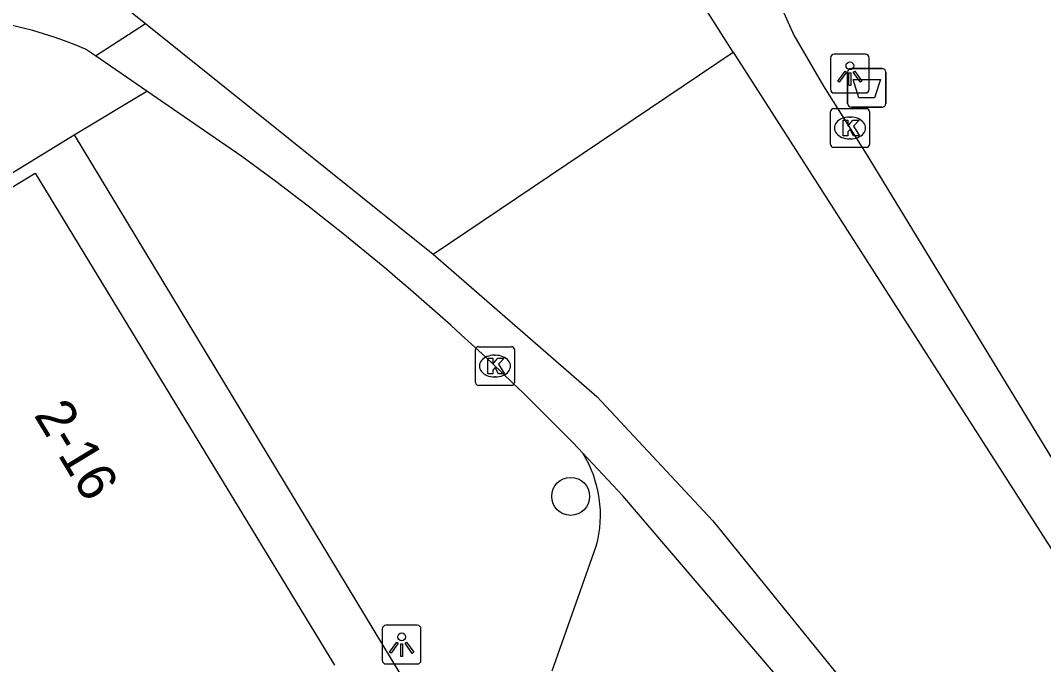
# Model space of a CAD drawing. Extents: x 159888 to 160757, y 384031 to 384746.
# Drawn here: x 160266.23 to 160292.59, y 384671.18 to 384687.78 of the extents above; entities that cross this region are included whole.
import ezdxf

# ---------------------------------------------------------------- set-up
doc = ezdxf.new("R2010")
doc.units = 0
for name, color, linetype in [('IMGEO_Afvalbak', 7, 'Continuous'), ('IMGEO_Boom', 7, 'Continuous'), ('IMGEO_Fietspad_open', 7, 'Continuous'), ('IMGEO_Kolk', 7, 'Continuous'), ('IMGEO_Lichtpunt', 7, 'Continuous'), ('IMGEO_Pand', 7, 'Continuous'), ('IMGEO_Pand_nummerreeks', 7, 'Continuous'), ('IMGEO_Rijbaan_lokaal_gesloten', 7, 'Continuous'), ('IMGEO_Rijbaan_lokaal_open', 7, 'Continuous'), ('IMGEO_Voetpad_open', 7, 'Continuous')]:
    doc.layers.add(name, color=color, linetype=linetype)

msp = doc.modelspace()

# ---------------------------------------------------------------- linework, layer by layer
at = {"layer": 'IMGEO_Afvalbak'}
for p, q in [((160287.54, 384685.64), (160287.54, 384686.44)), ((160287.54, 384686.44), (160287.54, 384685.64)), ((160287.64, 384686.54), (160288.43, 384686.54)), ((160288.43, 384686.54), (160287.64, 384686.54)), ((160288.53, 384686.44), (160288.53, 384685.64)), ((160288.53, 384685.64), (160288.53, 384686.44)), ((160288.43, 384685.54), (160287.64, 384685.54)), ((160287.64, 384685.54), (160288.43, 384685.54))]:
    msp.add_line(p, q, dxfattribs=at)
msp.add_lwpolyline([(160287.683, 384686.254), (160288.387, 384686.254), (160288.238, 384685.784), (160287.832, 384685.784), (160287.683, 384686.254)], dxfattribs=at)
for centre, start, end in [((160287.64, 384686.44), 90, 180), ((160287.64, 384686.44), 90, 180), ((160288.43, 384686.44), 0, 90), ((160288.43, 384686.44), 360, 90), ((160287.64, 384685.64), 180, 270), ((160287.64, 384685.64), 180, 270), ((160288.43, 384685.64), 270, 0), ((160288.43, 384685.64), 270, 0)]:
    msp.add_arc(centre, 0.1, start, end, dxfattribs=at)
at = {"layer": 'IMGEO_Boom'}
msp.add_circle((160280.406, 384675.514), 0.489, dxfattribs=at)
at = {"layer": 'IMGEO_Fietspad_open'}
msp.add_lwpolyline([(160268.158, 384686.863), (160267.903, 384687.038)], dxfattribs=at)
msp.add_arc((160263.758, 384677.463), 10.433, 66.5927, 91.8798, dxfattribs=at)
at = {"layer": 'IMGEO_Kolk'}
for p, q in [((160287.103, 384684.58), (160287.103, 384685.432)), ((160287.178, 384685.506), (160288.03, 384685.506)), ((160288.104, 384685.432), (160288.104, 384684.58)), ((160287.591, 384685.286), (160287.616, 384685.286)), ((160287.614, 384684.726), (160287.589, 384684.726)), ((160288.03, 384684.506), (160287.178, 384684.506)), ((160278.029, 384679.371), (160278.881, 384679.371)), ((160277.954, 384678.445), (160277.954, 384679.297)), ((160278.442, 384679.151), (160278.467, 384679.151)), ((160278.955, 384679.297), (160278.955, 384678.445)), ((160278.465, 384678.591), (160278.44, 384678.591)), ((160278.881, 384678.371), (160278.029, 384678.371))]:
    msp.add_line(p, q, dxfattribs=at)
for points in [[(160287.103, 384684.58), (160287.103, 384685.432)], [(160287.178, 384685.506), (160288.03, 384685.506)], [(160288.104, 384685.432), (160288.104, 384684.58)], [(160287.424, 384685.206), (160287.547, 384685.206), (160287.547, 384685.055), (160287.677, 384685.206), (160287.841, 384685.206), (160287.695, 384685.055), (160287.848, 384684.806), (160287.696, 384684.806), (160287.611, 384684.97), (160287.547, 384684.903), (160287.547, 384684.806), (160287.424, 384684.806), (160287.424, 384685.206)], [(160288.03, 384684.506), (160287.178, 384684.506)], [(160278.029, 384679.371), (160278.881, 384679.371)], [(160277.954, 384678.445), (160277.954, 384679.297)], [(160278.275, 384679.071), (160278.398, 384679.071), (160278.398, 384678.92), (160278.528, 384679.071), (160278.692, 384679.071), (160278.546, 384678.92), (160278.699, 384678.671), (160278.547, 384678.671), (160278.462, 384678.835), (160278.398, 384678.768), (160278.398, 384678.671), (160278.275, 384678.671), (160278.275, 384679.071)], [(160278.955, 384679.297), (160278.955, 384678.445)], [(160278.881, 384678.371), (160278.029, 384678.371)]]:
    msp.add_lwpolyline(points, dxfattribs=at)
for centre, start, end in [((160287.18, 384685.43), 91.552, 178.448), ((160287.18, 384685.43), 91.552, 178.448), ((160288.028, 384685.43), 1.552, 88.448), ((160288.028, 384685.43), 1.552, 88.448), ((160287.18, 384684.582), 181.552, 268.448), ((160287.18, 384684.582), 181.552, 268.448), ((160288.028, 384684.582), 271.552, 358.448), ((160288.028, 384684.582), 271.552, 358.448), ((160278.031, 384679.295), 91.552, 178.448), ((160278.031, 384679.295), 91.552, 178.448), ((160278.879, 384679.295), 1.552, 88.448), ((160278.879, 384679.295), 1.552, 88.448), ((160278.031, 384678.447), 181.552, 268.448), ((160278.031, 384678.447), 181.552, 268.448), ((160278.879, 384678.447), 271.552, 358.448), ((160278.879, 384678.447), 271.552, 358.448)]:
    msp.add_arc(centre, 0.0765, start, end, dxfattribs=at)
for centre, major_axis, ratio, start_param, end_param in [((160287.59, 384685.006), (-0.387, 0.002), 0.722429, 4.712389, 7.853982), ((160287.615, 384685.006), (-0.39, 0.002), 0.717154, 1.570796, 4.712389), ((160278.441, 384678.871), (-0.387, 0.002), 0.722429, 4.712389, 7.853982), ((160278.466, 384678.871), (-0.39, 0.002), 0.717154, 1.570796, 4.712389)]:
    msp.add_ellipse(centre, major_axis=major_axis, ratio=ratio, start_param=start_param, end_param=end_param, dxfattribs=at)
at = {"layer": 'IMGEO_Lichtpunt'}
for p, q in [((160287.101, 384686.81), (160287.101, 384686.003)), ((160287.101, 384686.81), (160287.101, 384686.003)), ((160288.003, 384686.905), (160287.195, 384686.905)), ((160288.003, 384686.905), (160287.195, 384686.905)), ((160288.097, 384686.003), (160288.097, 384686.81)), ((160288.097, 384686.003), (160288.097, 384686.81)), ((160287.195, 384685.909), (160288.003, 384685.909)), ((160287.195, 384685.909), (160288.003, 384685.909)), ((160275.552, 384672.097), (160275.552, 384671.29)), ((160275.552, 384672.097), (160275.552, 384671.29)), ((160276.454, 384672.192), (160275.646, 384672.192)), ((160276.454, 384672.192), (160275.646, 384672.192)), ((160276.548, 384671.29), (160276.548, 384672.097)), ((160276.548, 384671.29), (160276.548, 384672.097)), ((160275.646, 384671.196), (160276.454, 384671.196)), ((160275.646, 384671.196), (160276.454, 384671.196))]:
    msp.add_line(p, q, dxfattribs=at)
for points in [[(160287.475, 384686.474), (160287.514, 384686.446), (160287.326, 384686.184), (160287.288, 384686.211), (160287.475, 384686.474)], [(160287.687, 384686.446), (160287.725, 384686.473), (160287.912, 384686.211), (160287.873, 384686.183), (160287.687, 384686.446)], [(160287.577, 384686.426), (160287.624, 384686.426), (160287.624, 384686.104), (160287.577, 384686.104), (160287.577, 384686.426)], [(160275.926, 384671.761), (160275.965, 384671.733), (160275.777, 384671.471), (160275.739, 384671.498), (160275.926, 384671.761)], [(160276.028, 384671.713), (160276.075, 384671.713), (160276.075, 384671.391), (160276.028, 384671.391), (160276.028, 384671.713)], [(160276.138, 384671.733), (160276.176, 384671.76), (160276.363, 384671.498), (160276.324, 384671.47), (160276.138, 384671.733)]]:
    msp.add_lwpolyline(points, dxfattribs=at)
for centre in [(160287.6, 384686.608), (160276.051, 384671.895)]:
    msp.add_circle(centre, 0.0994, dxfattribs=at)
for centre, start, end in [((160287.195, 384686.81), 90, 180), ((160287.195, 384686.81), 90, 180), ((160288.003, 384686.81), 0, 90), ((160288.003, 384686.81), 0, 90), ((160287.195, 384686.003), 180, 270), ((160287.195, 384686.003), 180, 270), ((160288.003, 384686.003), 270, 0), ((160288.003, 384686.003), 270, 360), ((160275.646, 384672.097), 90, 180), ((160275.646, 384672.097), 90, 180), ((160276.454, 384672.097), 0, 90), ((160276.454, 384672.097), 0, 90), ((160275.646, 384671.29), 180, 270), ((160275.646, 384671.29), 180, 270), ((160276.454, 384671.29), 270, 0), ((160276.454, 384671.29), 270, 360)]:
    msp.add_arc(centre, 0.0946, start, end, dxfattribs=at)
at = {"layer": 'IMGEO_Pand'}
msp.add_lwpolyline([(160259.438, 384677.719), (160259.575, 384677.802), (160260.082, 384676.969), (160265.09, 384680.017), (160264.228, 384682.398), (160266.608, 384683.846), (160274.323, 384671.167)], dxfattribs=at)
at = {"layer": 'IMGEO_Rijbaan_lokaal_gesloten'}
for points in [[(160284.589, 384686.958), (160280.891, 384692.793)], [(160266.214, 384690.293), (160269.451, 384687.696)], [(160269.451, 384687.696), (160276.866, 384681.757)], [(160276.866, 384681.757), (160284.589, 384686.958)]]:
    msp.add_lwpolyline(points, dxfattribs=at)
at = {"layer": 'IMGEO_Rijbaan_lokaal_open'}
for points in [[(160282.746, 384695.908), (160282.752, 384695.89), (160283.248, 384694.297), (160284.135, 384691.929), (160285.132, 384689.679), (160286.159, 384687.4), (160286.924, 384686.085), (160288.021, 384684.341), (160293.588, 384675.207)], [(160268.158, 384686.863), (160269.451, 384687.696)], [(160284.589, 384686.958), (160294.325, 384671.764), (160295.305, 384672.391)], [(160269.481, 384685.954), (160268.158, 384686.863)], [(160271.929, 384684.273), (160269.481, 384685.954)], [(160276.866, 384681.757), (160281.076, 384678.085), (160284.067, 384674.885), (160290.756, 384666.631), (160289.959, 384665.862)], [(160289.827, 384666.03), (160289.409, 384666.564), (160281.752, 384675.529), (160280.72, 384676.628)]]:
    msp.add_lwpolyline(points, dxfattribs=at)
msp.add_arc((160233.847, 384631.606), 64.993, 43.84636, 54.13063, dxfattribs=at)
at = {"layer": 'IMGEO_Voetpad_open'}
for points in [[(160267.612, 384684.826), (160269.481, 384685.954)], [(160258.508, 384679.247), (160267.612, 384684.826)], [(160267.612, 384684.826), (160315.278, 384605.986), (160314.349, 384605.388)], [(160279.926, 384671.019), (160281.066, 384674.234)]]:
    msp.add_lwpolyline(points, dxfattribs=at)
msp.add_arc((160278.129, 384675.031), 3.044, 344.8115, 31.6363, dxfattribs=at)

# ---------------------------------------------------------------- texts
at = {"layer": 'IMGEO_Pand_nummerreeks'}
msp.add_text('2-16', height=1, rotation=301.1192, dxfattribs=at).set_placement((160266.56, 384677.612))

doc.saveas('drawing.dxf')
